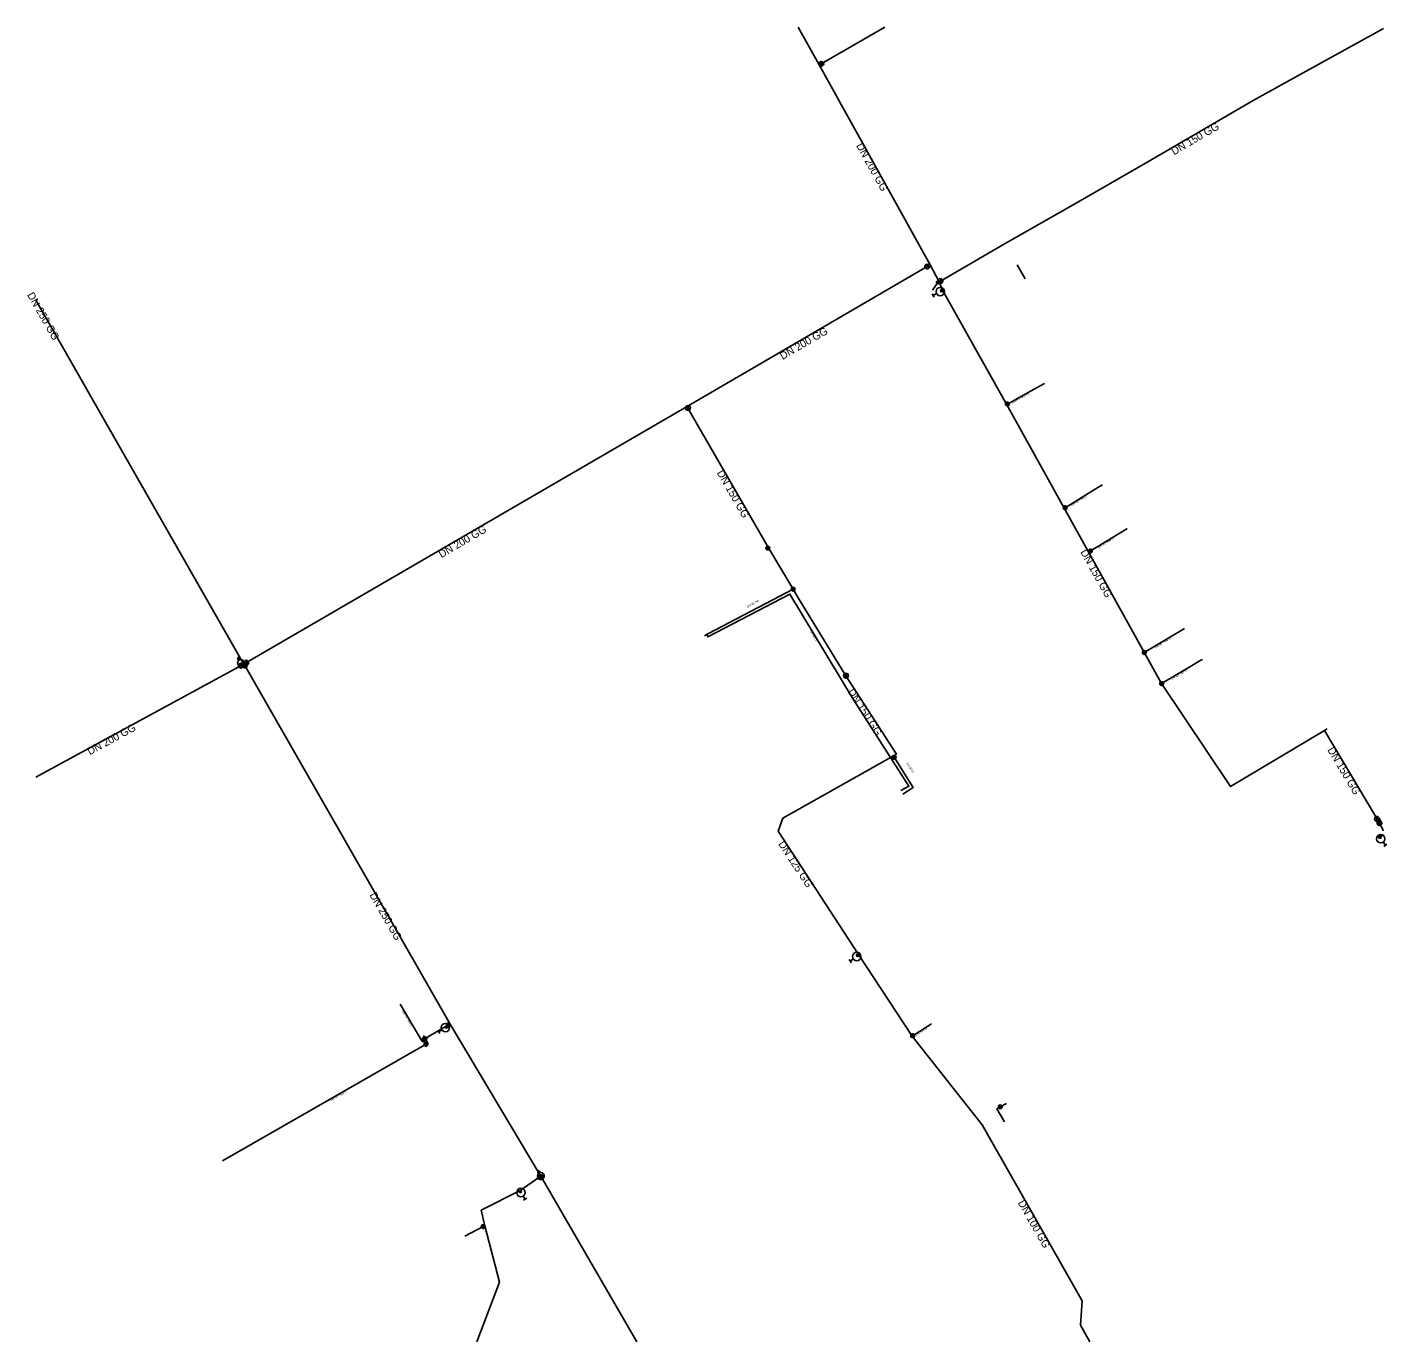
# Model space of a CAD drawing. Extents: x -443912 to -443626, y -1122546 to -1122269.
import ezdxf

# ---------------------------------------------------------------- set-up
doc = ezdxf.new("R2010")
doc.units = 0
for name, color, linetype in [('_hydrantova_odbocka_', 7, 'Continuous'), ('_kalosvod_', 7, 'Continuous'), ('_pripojka_priblizne_', 7, 'Continuous'), ('_voda_smvak_prevzato_z_dokumentace_', 7, 'Continuous'), ('Default', 7, 'Continuous'), ('MoLevel 27', 7, 'Continuous'), ('MoLevel 28', 7, 'Continuous'), ('MoLevel 30', 7, 'Continuous'), ('MoLevel 32', 7, 'Continuous'), ('MoLevel 46', 7, 'Continuous'), ('MoLevel 53', 7, 'Continuous')]:
    doc.layers.add(name, color=color, linetype=linetype)

# ---------------------------------------------------------------- blocks, each defined once
blk = doc.blocks.new('_uzaver_')
at = {"layer": 'Default'}
for p, q in [((-0.000035, -0.000035), (0.000035, 0.000035)), ((0.000035, -0.000035), (-0.000035, 0.000035))]:
    blk.add_line(p, q, dxfattribs=at)
for radius in [0.00005, 0.0000025]:
    blk.add_circle((0, 0), radius, dxfattribs=at)
blk = doc.blocks.new('_uzaver_pripojka_')
at = {"layer": 'Default'}
for p, q in [((-0.000035, -0.000035), (0.000035, 0.000035)), ((0.000035, -0.000035), (-0.000035, 0.000035))]:
    blk.add_line(p, q, dxfattribs=at)
for radius in [0.00005, 0.0000025]:
    blk.add_circle((0, 0), radius, dxfattribs=at)
blk = doc.blocks.new('_hydrant_voda_')
at = {"layer": 'Default'}
for p, q in [((-0.000023, 0.000095), (0.000023, 0.000095)), ((0, 0.000095), (0, 0.00005))]:
    blk.add_line(p, q, dxfattribs=at)
blk.add_circle((0, 0), 0.00005, dxfattribs=at)
blk = doc.blocks.new('_sachta_voda_')
at = {"layer": 'Default'}
blk.add_line((-0.00001, 0.000045), (0.00001, 0.000045), dxfattribs=at)
blk.add_lwpolyline([(-0.00001, 0.000035), (-0.00001, 0.00005), (0, 0.000065), (0.00001, 0.00005), (0.00001, 0.000035)], dxfattribs=at)
blk.add_circle((0, 0), 0.000035, dxfattribs=at)

msp = doc.modelspace()

# ---------------------------------------------------------------- linework, layer by layer
at = {"layer": '_hydrantova_odbocka_'}
for points in [[(-443720.04, -1122324.98), (-443719.72, -1122324.77), (-443719.57, -1122324.66)], [(-443626.81, -1122439.28), (-443627.6, -1122439.72), (-443627.41, -1122440.08)], [(-443737.58, -1122464.84), (-443737.38, -1122464.6), (-443737.21, -1122464.43)], [(-443824.07, -1122479.8), (-443823.84, -1122479.68), (-443823.73, -1122479.63), (-443823.82, -1122479.46)], [(-443808.39, -1122514.09), (-443808.3, -1122514.27), (-443808.21, -1122514.48)]]:
    msp.add_lwpolyline(points, dxfattribs=at)
at = {"layer": '_kalosvod_'}
msp.add_lwpolyline([(-443721.65, -1122324.69), (-443720.57, -1122323.07), (-443720.24, -1122322.91)], dxfattribs=at)
at = {"layer": '_pripojka_priblizne_'}
for p, q in [((-443703.89, -1122319.32), (-443702.2, -1122322.3)), ((-443750.96, -1122387.58), (-443768.73, -1122396.91)), ((-443671.98, -1122397.84), (-443668.64, -1122395.86)), ((-443769.15, -1122397.13), (-443769.57, -1122397.36)), ((-443768.73, -1122396.91), (-443769.15, -1122397.13)), ((-443677.13, -1122400.89), (-443671.98, -1122397.84)), ((-443673.49, -1122407.44), (-443668.25, -1122404.34)), ((-443725.95, -1122481.58), (-443721.89, -1122478.98))]:
    msp.add_line(p, q, dxfattribs=at)
for points in [[(-443701.52, -1122346.18), (-443698.24, -1122344.35), (-443698.1, -1122344.38)], [(-443706.12, -1122348.67), (-443705.92, -1122348.63), (-443701.52, -1122346.18)], [(-443693.96, -1122370.58), (-443693.75, -1122370.45), (-443689.28, -1122367.68)], [(-443689.28, -1122367.68), (-443686.53, -1122365.98), (-443685.94, -1122365.64)], [(-443684.01, -1122376.83), (-443680.81, -1122374.88), (-443680.7, -1122374.79)], [(-443688.84, -1122379.79), (-443688.48, -1122379.56), (-443684.01, -1122376.83)], [(-443769.14, -1122397.13), (-443768.9, -1122397.59), (-443751.64, -1122388.66), (-443738.36, -1122410.7), (-443726.61, -1122429.02), (-443728.29, -1122429.9)], [(-443668.25, -1122404.34), (-443665.22, -1122402.54), (-443664.91, -1122402.38)], [(-443729.9, -1122422.65), (-443729.72, -1122422.94), (-443725.72, -1122429.26), (-443727.91, -1122430.69)], [(-443828.31, -1122482.12), (-443828.69, -1122482.34), (-443829.06, -1122482.57), (-443833.56, -1122474.87)], [(-443828.31, -1122482.12), (-443823.91, -1122479.51), (-443823.42, -1122479.24), (-443823.09, -1122479.06)], [(-443828.31, -1122482.12), (-443827.75, -1122483.06), (-443870.93, -1122507.84)], [(-443706.52, -1122499.62), (-443708.12, -1122496.87), (-443707.41, -1122496.46), (-443706.13, -1122495.73)], [(-443815.79, -1122521.48), (-443816.13, -1122521.66), (-443819.96, -1122523.67)]]:
    msp.add_lwpolyline(points, dxfattribs=at)
at = {"layer": '_voda_smvak_prevzato_z_dokumentace_'}
for p, q in [((-443745.47, -1122277.28), (-443749.88, -1122269.37)), ((-443731.65, -1122269.37), (-443745.04, -1122277.09)), ((-443745.04, -1122277.09), (-443745.47, -1122277.28)), ((-443745.47, -1122277.28), (-443722.18, -1122319.36)), ((-443722.78, -1122319.72), (-443722.18, -1122319.36)), ((-443722.18, -1122319.36), (-443720.24, -1122322.91)), ((-443773.38, -1122349.25), (-443722.78, -1122319.72)), ((-443720.24, -1122322.91), (-443719.99, -1122322.78)), ((-443720.24, -1122322.91), (-443719.57, -1122324.66)), ((-443910.19, -1122326.8), (-443866.87, -1122402.68)), ((-443865.57, -1122402.82), (-443773.38, -1122349.25)), ((-443773.38, -1122349.25), (-443773.07, -1122349.47)), ((-443867.53, -1122403.91), (-443910.19, -1122427.14)), ((-443867.07, -1122403.66), (-443867.53, -1122403.91)), ((-443866.5, -1122403.35), (-443867.07, -1122403.66)), ((-443866.87, -1122402.68), (-443866.5, -1122403.35)), ((-443866.5, -1122403.35), (-443865.97, -1122403.04)), ((-443866.5, -1122403.35), (-443866.27, -1122403.65)), ((-443866.27, -1122403.65), (-443865.99, -1122404.13)), ((-443865.97, -1122403.04), (-443865.57, -1122402.82)), ((-443739.85, -1122405.77), (-443729.2, -1122422.26)), ((-443639.23, -1122417.33), (-443638.65, -1122416.92)), ((-443639.23, -1122417.33), (-443628.53, -1122435.34)), ((-443628.53, -1122435.34), (-443628.2, -1122435.88)), ((-443628.2, -1122435.88), (-443627.95, -1122436.32)), ((-443627.42, -1122436.01), (-443627.95, -1122436.32)), ((-443627.95, -1122436.32), (-443627.82, -1122436.54)), ((-443627.82, -1122436.54), (-443627.69, -1122436.78)), ((-443627.69, -1122436.78), (-443627.29, -1122437.5)), ((-443627.29, -1122437.5), (-443626.81, -1122438.39)), ((-443725.95, -1122481.58), (-443737.21, -1122464.43)), ((-443808.39, -1122514.09), (-443804.2, -1122511.22)), ((-443804.34, -1122510.5), (-443803.98, -1122511.09)), ((-443804.2, -1122511.22), (-443803.98, -1122511.09)), ((-443803.98, -1122511.09), (-443803.88, -1122511.27)), ((-443803.88, -1122511.27), (-443803.73, -1122511.53)), ((-443803.73, -1122511.53), (-443783.81, -1122545.88))]:
    msp.add_line(p, q, dxfattribs=at)
for points in [[(-443719.99, -1122322.78), (-443706.39, -1122314.9), (-443691.62, -1122306.46), (-443676.39, -1122297.7), (-443654.21, -1122284.79), (-443645.78, -1122280.08), (-443626.81, -1122269.61)], [(-443719.57, -1122324.66), (-443706.12, -1122348.67), (-443673.49, -1122407.44), (-443659.03, -1122429.09), (-443639.23, -1122417.33)], [(-443773.07, -1122349.47), (-443756.11, -1122378.86), (-443750.96, -1122387.58), (-443749.91, -1122389.38), (-443739.85, -1122405.77)], [(-443865.99, -1122404.13), (-443823.09, -1122479.06), (-443804.34, -1122510.5)], [(-443737.21, -1122464.43), (-443754.14, -1122438.45), (-443753.1, -1122435.77), (-443729.2, -1122422.26)], [(-443688.59, -1122545.88), (-443690.53, -1122542.42), (-443690.21, -1122537.25), (-443711.21, -1122500.24), (-443725.95, -1122481.58)], [(-443817.45, -1122545.88), (-443812.71, -1122533.31), (-443815.79, -1122521.48), (-443816.59, -1122518.21), (-443808.39, -1122514.09)]]:
    msp.add_lwpolyline(points, dxfattribs=at)

# ---------------------------------------------------------------- block references
at = {"layer": 'MoLevel 27'}
for p, xscale, yscale, rotation in [((-443745.04, -1122277.09), 10000, 10000, 31.52043888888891), ((-443722.78, -1122319.72), 10000, 10000, -149.8222378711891), ((-443719.99, -1122322.78), 10000, 10000, 29.580672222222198), ((-443720.57, -1122323.07), 5000, 5000, -150.67034756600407), ((-443719.72, -1122324.77), 5000.000000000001, 5000, -153.1975367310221), ((-443773.07, -1122349.47), 10000.000000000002, 10000.000000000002, -59.685700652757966), ((-443865.97, -1122403.04), 10000, 10000.000000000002, 30.147995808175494), ((-443867.07, -1122403.66), 10000.000000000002, 10000, -151.8832777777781), ((-443866.27, -1122403.65), 10000, 10000.000000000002, -59.90926006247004), ((-443739.85, -1122405.77), 10000, 10000.000000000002, -55.74398611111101), ((-443628.2, -1122435.88), 10000, 9999.999999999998, 120.722291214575), ((-443627.69, -1122436.78), 9999.999999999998, 9999.999999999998, -59.276272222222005), ((-443737.38, -1122464.6), 5000, 5000, -140.45559102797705), ((-443823.84, -1122479.68), 5000, 5000, -150.60461738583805), ((-443804.2, -1122511.22), 10000, 10000.000000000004, -150.5469055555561), ((-443803.88, -1122511.27), 10000, 10000, -59.91685317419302), ((-443808.3, -1122514.27), 5000, 4999.999999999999, -64.544861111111)]:
    msp.add_blockref('_uzaver_', p, dxfattribs=dict(at, xscale=xscale, yscale=yscale, rotation=rotation))
at = {"layer": 'MoLevel 27', "xscale": 5000, "yscale": 5000}
msp.add_blockref('_uzaver_', (-443627.6, -1122439.72), dxfattribs=at)
at = {"layer": 'MoLevel 28'}
for p, xscale, yscale, rotation in [((-443720.04, -1122324.98), 17636.684303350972, 17636.68430335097, 119.60187148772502), ((-443627.41, -1122440.08), 17636.68430335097, 17636.684303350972, -144.60465694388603), ((-443737.58, -1122464.84), 17636.68430335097, 17636.68430335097, 125.3143), ((-443824.07, -1122479.8), 17636.68430335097, 17636.68430335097, 122.34727387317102), ((-443808.21, -1122514.48), 17636.68430335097, 17636.684303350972, -148.25429455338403)]:
    msp.add_blockref('_hydrant_voda_', p, dxfattribs=dict(at, xscale=xscale, yscale=yscale, rotation=rotation))
at = {"layer": 'MoLevel 30'}
for p, xscale, yscale, rotation in [((-443867.08, -1122403.1), 20000, 20000, 27.488971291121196), ((-443828.31, -1122482.12), 10000, 10000.000000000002, 30.65016322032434), ((-443803.99, -1122510.99), 20000, 19999.999999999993, 29.1098555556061)]:
    msp.add_blockref('_sachta_voda_', p, dxfattribs=dict(at, xscale=xscale, yscale=yscale, rotation=rotation))
at = {"layer": 'MoLevel 53'}
for p, xscale, yscale, rotation in [((-443705.92, -1122348.63), 7999.999999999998, 7999.999999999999, 29.13055957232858), ((-443693.75, -1122370.45), 7999.999999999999, 7999.999999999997, 31.76221196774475), ((-443756.29, -1122378.93), 7999.999999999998, 7999.999999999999, -151.09081635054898), ((-443688.48, -1122379.56), 8000, 7999.999999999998, 31.390268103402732), ((-443750.96, -1122387.58), 7999.999999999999, 8000, -59.682080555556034), ((-443677.13, -1122400.89), 8000, 7999.999999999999, 30.63349162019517), ((-443673.49, -1122407.44), 7999.999999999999, 7999.999999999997, 30.64686963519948), ((-443729.72, -1122422.94), 7999.999999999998, 8000, -55.743244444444), ((-443823.42, -1122479.24), 8000, 7999.999999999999, 31.686194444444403), ((-443828.69, -1122482.34), 7999.999999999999, 7999.999999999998, -147.0305074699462), ((-443725.83, -1122481.51), 7999.999999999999, 7999.999999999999, 29.4083888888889), ((-443828.17, -1122483.3), 7999.999999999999, 8000, -150.14306640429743)]:
    msp.add_blockref('_uzaver_pripojka_', p, dxfattribs=dict(at, xscale=xscale, yscale=yscale, rotation=rotation))
at = {"layer": 'MoLevel 53', "xscale": 7999.999999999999, "yscale": 7999.999999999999}
for p in [(-443707.41, -1122496.46), (-443816.13, -1122521.66)]:
    msp.add_blockref('_uzaver_pripojka_', p, dxfattribs=at)

# ---------------------------------------------------------------- texts
at = {"layer": 'MoLevel 32'}
for s, rotation, p in [('DN 40 - 6/4 PE', 29.1306, (-443704.89, -1122348.57)), ('DN 40 - 6/4 O', 31.7622, (-443692.38, -1122370.14)), ('DN 40 - 6/4 O', 31.3903, (-443686.77, -1122379.05)), ('DN 80 PE', 27.7194, (-443760.56, -1122391.49)), ('DN 80 O', 301.0586, (-443747.51, -1122396.39)), ('DN 40 - 6/4 O', 30.6335, (-443674.82, -1122400.05)), ('DN 40 - 6/4 O', 30.6469, (-443671.34, -1122406.69)), ('DN 80 O', 302.3778, (-443727.18, -1122424.25)), ('DN 40 - 6/4 O', 300.2932, (-443833.25, -1122476.31)), ('DN 100 O', 32.6372, (-443725.07, -1122481.56)), ('DN 40 - 6/4 O', 29.8569, (-443848.13, -1122495.28))]:
    msp.add_text(s, height=0.455, rotation=rotation, dxfattribs=at).set_placement(p)
at = {"layer": 'MoLevel 46'}
for s, rotation, p in [('DN 150 GG', 30.2046, (-443670.88, -1122296.32)), ('DN 200 GG', 298.9573, (-443737.76, -1122294.27)), ('DN 250 GG', 299.7225, (-443912.09, -1122325.68)), ('DN 200 GG', 30.2692, (-443753.18, -1122339.39)), ('DN 150 GG', 299.9878, (-443767.07, -1122363.09)), ('DN 200 GG', 30.157, (-443824.94, -1122381.07)), ('DN 150 GG', 299.0397, (-443690.62, -1122379.75)), ('DN 150 GG', 302.85, (-443739.58, -1122409.15)), ('DN 200 GG', 28.5659, (-443898.84, -1122422.53)), ('DN 150 GG', 300.7253, (-443638.69, -1122421.38)), ('DN 125 GG', 303.0807, (-443754.16, -1122441.15)), ('DN 250 GG', 299.7935, (-443840.1, -1122451.91)), ('DN 100 GG', 299.5695, (-443703.76, -1122516.63))]:
    msp.add_text(s, height=1.605, rotation=rotation, dxfattribs=at).set_placement(p)

doc.saveas('drawing.dxf')
